// Mitsubishi GX Works2 project: 正反转标准程序_1s   PLC: FX1S

PROGRAM MAIN
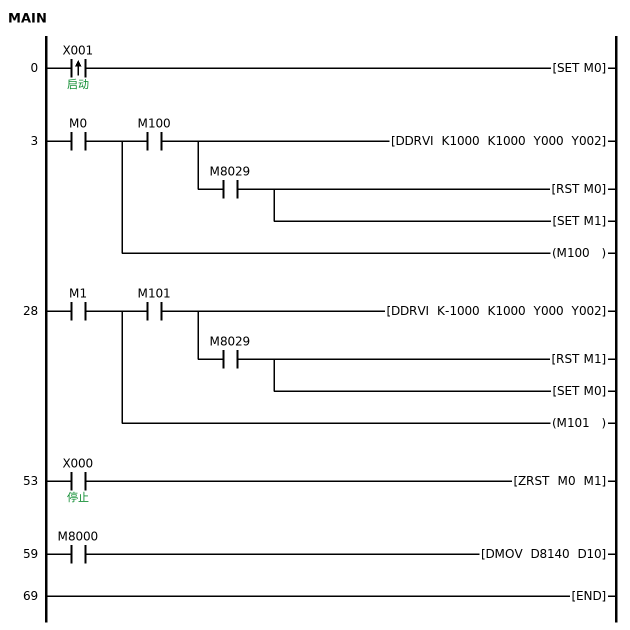
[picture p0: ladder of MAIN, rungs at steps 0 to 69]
0     LDP     X001  ; 启动
      SET     M0
3     LD      M0
      MPS
      AND     M100
      DDRVI   K1000 K1000 Y000 Y002
      AND     M8029
      RST     M0
      SET     M1
      MPP
      OUT     M100
28    LD      M1
      MPS
      AND     M101
      DDRVI   K-1000 K1000 Y000 Y002
      AND     M8029
      RST     M1
      SET     M0
      MPP
      OUT     M101
53    LD      X000  ; 停止
      ZRST    M0 M1
59    LD      M8000
      DMOV    D8140 D10
69    END
END_PROGRAM
